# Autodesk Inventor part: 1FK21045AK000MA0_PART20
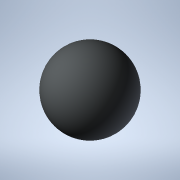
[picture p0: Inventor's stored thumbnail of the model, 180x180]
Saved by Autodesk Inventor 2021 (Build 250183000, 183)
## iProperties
Created: 2025-04
Part Number: 1FK21045AK000MA0_PART20
Material: Generic
Catalog Web Link: www.3dfindit.com
Description: -Servo synchronous motor
Document SubType Name: Modeling
Designer: psAdmin
Mass: 0.137258 g
Surface Area: 1.2868 cm^2
Volume: 0.137258 cm^3
Density: 1 g/cm^3
Appearance: PSOLRGB-212-217-219
Category: PARTsolutions
Title: 1FK21045AK000MA0_PART20
Author: Cadenas PARTsolutions
Comments: Servo synchronous motor
Sending System: PARTsolutions
Preprocessor: ST-DEVELOPER v19.3
PSOL_IDENT_0: {$CADENAS_DATA/23d-libs/siemens_ag/_cat_/3d/2f/1fk21045ak000ma0.prj},216 {VTYP=3D},{NB=1FK21045AK000
PSOL_IDENT_1: MA0_PART20},{LINA=1FK21045AK000MA0_PART20},{NN=1FK21045AK000MA0_PART20},{NOPRJ=TRUE},{DATE=19.08.202
PSOL_IDENT_2: 5 14:00:34},{GEOMDATE=30.07.2025 02:01:24},{VERSION=},{LINEID=10},{WBVAR=},{WBNUMERIC=}  {NB=1FK2104
PSOL_IDENT_3: 5AK000MA0_PART20},{LINA=1FK21045AK000MA0_PART20},{KT=DUMMY},{PREVIEW=../../../_pool_/a9/69/p_d211_xx
PSOL_IDENT_4: _00818j.png},{DESCSHORT=SIMOTICS S-1FK2 HD, SINAMICS S210 3AC 400V-480V, 1.7 Nm, 6000 rpm},{DESCLONG=
PSOL_IDENT_5: SIMOTICS S-1FK2 HD servo motor M0=2.4 Nm; PN = 1.07 kW at nN=6000 rpm (380-480 V); PN = 0.75 kW at n
PSOL_IDENT_6: N=3000 rpm (200-240 V); degree of protection IP64; cylindrical shaft D19x40mm; absolute encoder 22-b
PSOL_IDENT_7: it + 12-bit multiturn (encoder AM22DQC); with OCC interface; plug size M17, rotatable; SIMOTICS S-1F
PSOL_IDENT_8: K2 servomotorfor a wide range of uses in industrial environments. SIMOTICS S‑1FK2 servomotors are co
PSOL_IDENT_9: mpact synchronous motors with a high dynamic performance that set themselves apart as a result of th
PSOL_IDENT_10: eir high power density, degree of protection and overload capability. The motors are available in tw
PSOL_IDENT_11: o variants: as High Dynamic variant (highest dynamic performance as a result of the low intrinsic mo
PSOL_IDENT_12: ment of inertia for applications demanding a high dynamic performance with low moved masses) - and a
PSOL_IDENT_13: s Compact variant (precise and stable closed-loop control for medium up to large moved masses as a r
PSOL_IDENT_14: esult of a medium intrinsic moment of inertia). SIMOTICSS‑1FK2 servomotors fully exploit their stren
PSOL_IDENT_15: gths in a system with the SINAMICSS210 frequency converter and simple connection using the one cable
PSOL_IDENT_16: connection (OCC). Advantages include the short control and positioning times, fast and precise corr
PSOL_IDENT_17: ection of disturbing quantities as well as stable control with a high dynamic performance. The servo
PSOL_IDENT_18: motors can be configured to address a wide range of requirements. For example with and without hold
PSOL_IDENT_19: ing brake, IP64 or IP65 degree of protection, singleturn or multiturn absolute encoders - to name ju
PSOL_IDENT_20: st a few. Further, the servomotors are available in different shaft heights extending from 20 to 100
PSOL_IDENT_21: . A shaft sealing ring is available to achieve an IP65 degree of protection and for subsequent mount
PSOL_IDENT_22: ing at the motor or as spare part. SIMOTICS - the optimum motor for each and every motion control ap
PSOL_IDENT_23: plication.},{INTNO=804766789342},{SUPPLIERALTNO=1FK2104-5AK00-0MA0},{MANUID=1FK21045AK000MA0},{MANUN
PSOL_IDENT_24: AME=Siemens},{MANUTYPEDESC=Synchronous motor 1FK2-HD 2,39 Nm},{AAU732=SIMOTICS},{AAO057=S-1FK2},{AAU
PSOL_IDENT_25: 734=SIMOTICS S-1FK2 HD servo motor M0=2.4 Nm; PN = 1.07 kW at nN=6000 rpm (380-480 V); PN = 0.75 kW
PSOL_IDENT_26: at nN=3000 rpm (200-240 V); degree of protection IP64; cylindrical shaft D19x40mm; absolute encoder
PSOL_IDENT_27: 22-bit + 12-bit multiturn (encoder AM22DQC); with OCC interface; plug size M17, rotatable;},{AAW338=
PSOL_IDENT_28: Synchronous motor 1FK2-HD 2,39 Nm},{AAO742=SIMOTICS},{AAO663=4042948691151},{NOCUPEROU=1},{PRICEQUAN
PSOL_IDENT_29: TITY=1},{QUANTITYMIN=1},{QUANTITYINT=1},{CTN=85015100},{COO=DE},{AAO676=1FK2104-5AK00-0MA0},{AAO677=
PSOL_IDENT_30: Siemens AG},{ORDERUNIT=C62},{CONTENTUNIT=C62}
NB: 1FK21045AK000MA0_PART20
NT: Servo synchronous motor
NBSYN: $MANUID._PART20
LINA: 1FK21045AK000MA0_PART20
CATALOG: SIEMENS
PREVIEW: ../../../_pool_/a9/69/p_d211_xx_00818j.png
DESCSHORT: SIMOTICS S-1FK2 HD, SINAMICS S210 3AC 400V-480V, 1.7 Nm, 6000 rpm
DESCLONG: SIMOTICS S-1FK2 HD servo motor M0=2.4 Nm; PN = 1.07 kW at nN=6000 rpm (380-480 V); PN = 0.75 kW at nN=3000 rpm (200-240 V); degree of protection IP64; cylindric
INTNO: 804766789342
SUPPLIERALTNO: 1FK2104-5AK00-0MA0
MANUID: 1FK21045AK000MA0
MANUNAME: Siemens
MANUTYPEDESC: Synchronous motor 1FK2-HD 2,39 Nm
AAU732: SIMOTICS
AAO057: S-1FK2
AAU734: SIMOTICS S-1FK2 HD servo motor M0=2.4 Nm; PN = 1.07 kW at nN=6000 rpm (380-480 V); PN = 0.75 kW at nN=3000 rpm (200-240 V); degree of protection IP64; cylindric
AAW338: Synchronous motor 1FK2-HD 2,39 Nm
AAO742: SIMOTICS
AAO663: 4042948691151.0
NOCUPEROU: 1
PRICEQUANTITY: 1
QUANTITYMIN: 1
QUANTITYINT: 1
CTN: 85015100
COO: DE
ARTICLENO: 1FK21045AK000MA0_PART20
BOMINFO: 1FK21045AK000MA0_PART20
CREATOR: CADENAS GmbH
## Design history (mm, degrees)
feature "2025_04_17_15_39_51_0728"
body "Solid1"
